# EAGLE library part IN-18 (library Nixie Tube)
Indicator Tube (numeral height 40mm, no filter, side view)
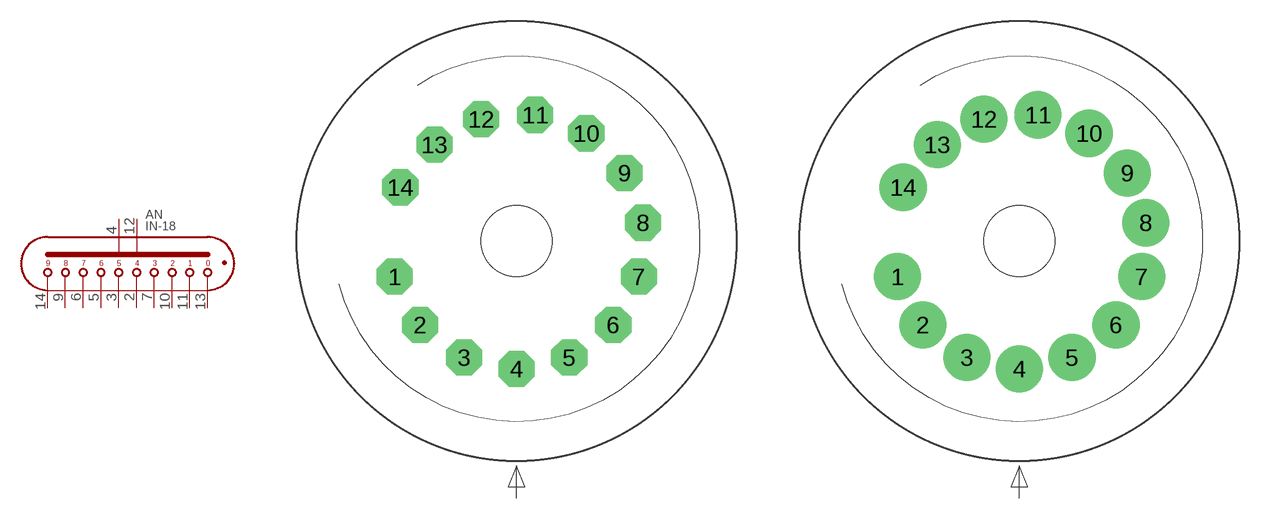
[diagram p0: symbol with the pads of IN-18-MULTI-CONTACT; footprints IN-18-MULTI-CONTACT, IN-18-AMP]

Designator prefix AN

## IN-18-B1-B_41.0002  [IN-18-MULTI-CONTACT]
2  4  pas
3  5  pas
4  A1  pas
5  6  pas
6  7  pas
7  3  pas
9  8  pas
10  2  pas
11  1  pas
12  A2  pas
13  0  pas
14  9  pas

## IN-18-1-380758-1  [IN-18-AMP]
Pads as for IN-18-MULTI-CONTACT

## Footprint IN-18-MULTI-CONTACT (pad centres in mm)
Socket with Multi-Contact (Mini-line Discret Socket Contact) Typ B1-B 41.0002
drill 1.1 pad 2.54 octagon: 1 -8.6,-2.5; 2 -6.8,-5.9; 3 -3.7,-8.2; 4 0,-9; 5 3.7,-8.2; 6 6.8,-5.9; 7 8.6,-2.5; 8 8.9,1.3; 9 7.6,4.8; 10 4.9,7.6; 11 1.3,8.9; 12 -2.5,8.6; 13 -5.8,6.8; 14 -8.2,3.8
hole 5 at 0,0

## Footprint IN-18-AMP (pad centres in mm)
Socket with AMP-Discret Socket Contact Typ 1-380758-1
drill 2.3 pad 3.2 round: 1 -8.6,-2.5; 2 -6.8,-5.9; 3 -3.7,-8.2; 4 0,-9; 5 3.7,-8.2; 6 6.8,-5.9; 7 8.6,-2.5; 8 8.9,1.3; 9 7.6,4.8; 10 4.9,7.6; 11 1.3,8.9; 12 -2.5,8.6; 13 -5.8,6.8; 14 -8.2,3.8
hole 5 at 0,0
